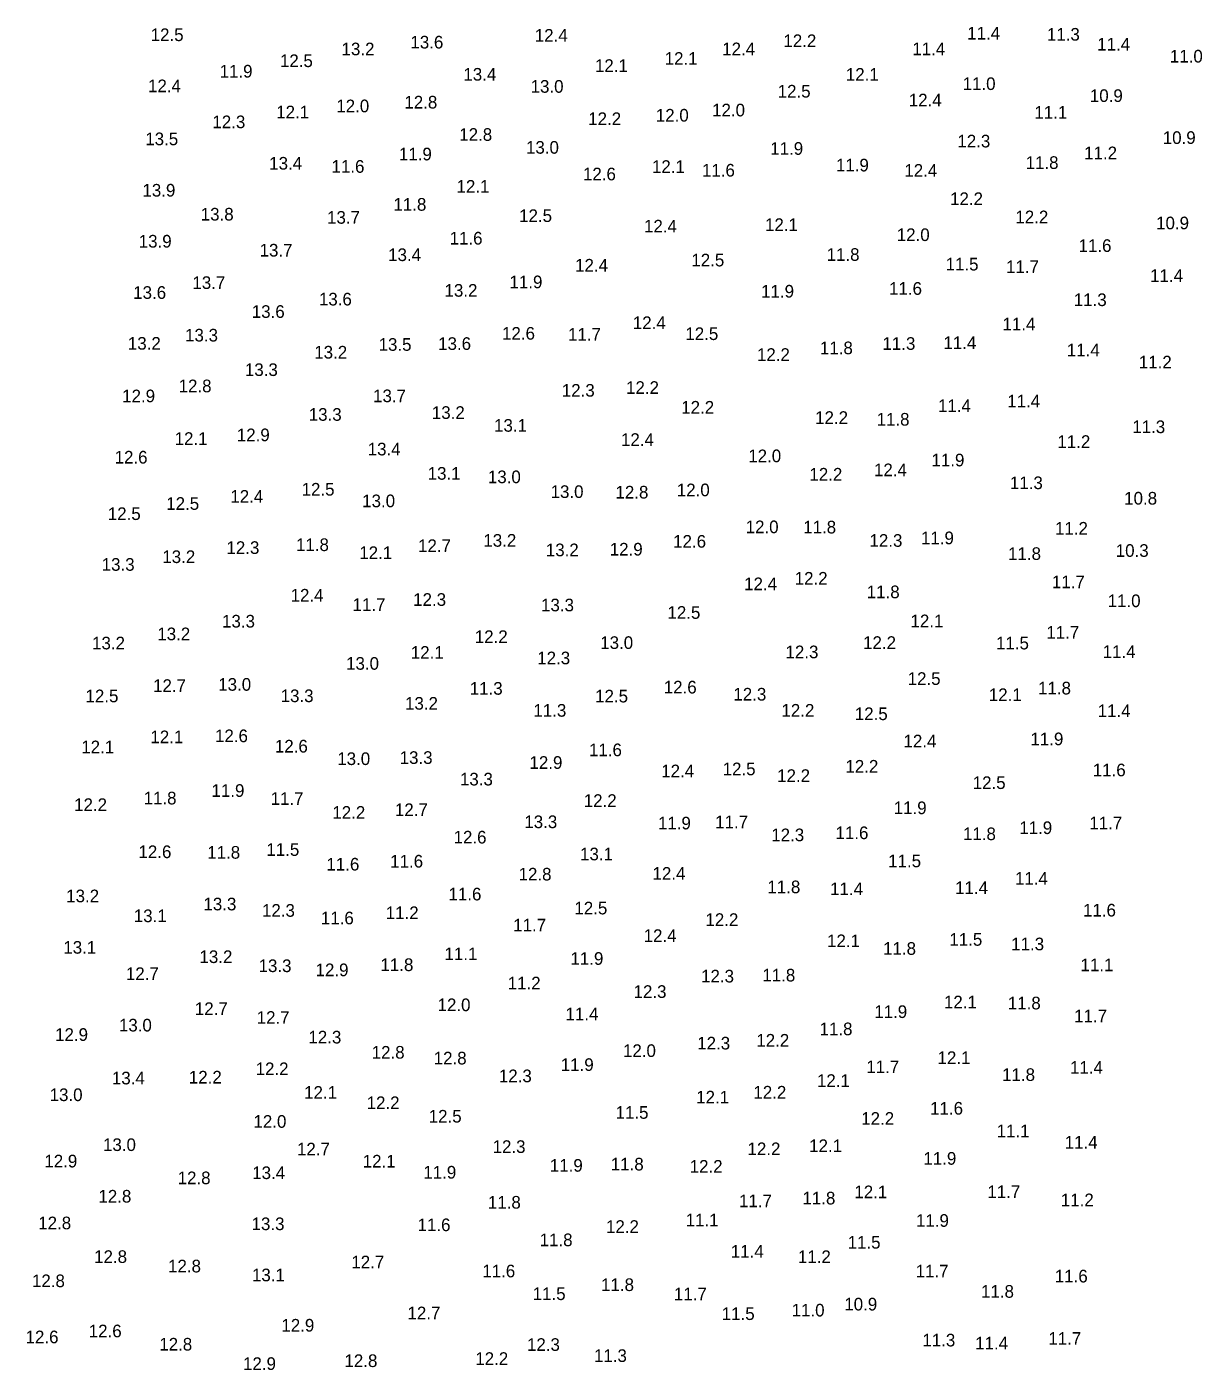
# Model space of a CAD drawing. Extents: x 1023796 to 1112670, y 656573 to 837340.
# Drawn here: x 1109778 to 1110243, y 670142 to 670673 of the extents above; entities that cross this region are included whole.
import ezdxf

# ---------------------------------------------------------------- set-up
doc = ezdxf.new("R2010")
doc.units = 0
doc.layers.add('V-TOPO-SOUN', color=7, linetype='Continuous')

msp = doc.modelspace()

# ---------------------------------------------------------------- texts
at = {"layer": 'V-TOPO-SOUN'}
for s, p in [('12.5 ', (1109827.08, 670667.24)), ('12.4 ', (1109978.96, 670667.01)), ('11.4 ', (1110149.93, 670667.86)), ('11.3 ', (1110181.44, 670667.41)), ('13.2 ', (1109902.55, 670661.62)), ('13.6 ', (1109929.78, 670664.31)), ('12.4 ', (1110053.06, 670661.65)), ('12.2 ', (1110077.26, 670664.86)), ('11.4 ', (1110128.21, 670661.67)), ('11.4 ', (1110201.33, 670663.51)), ('12.5 ', (1109878.19, 670656.96)), ('12.1 ', (1110030.31, 670657.86)), ('11.0 ', (1110230.06, 670658.76)), ('11.9 ', (1109854.34, 670652.82)), ('13.4 ', (1109950.73, 670651.6)), ('12.1 ', (1110002.74, 670655.04)), ('12.1 ', (1110101.95, 670651.57)), ('12.4 ', (1109826.04, 670647.03)), ('13.0 ', (1109977.31, 670646.81)), ('12.5 ', (1110074.99, 670644.91)), ('11.0 ', (1110148.12, 670647.89)), ('12.8 ', (1109927.4, 670640.58)), ('12.4 ', (1110126.83, 670641.41)), ('10.9 ', (1110198.43, 670643.16)), ('12.1 ', (1109876.73, 670636.7)), ('12.0 ', (1109900.48, 670639.1)), ('12.0 ', (1110026.81, 670635.41)), ('12.0 ', (1110049.06, 670637.47)), ('11.1 ', (1110176.49, 670636.57)), ('12.3 ', (1109851.49, 670632.8)), ('12.2 ', (1110000.08, 670634.04)), ('13.5 ', (1109824.95, 670626.07)), ('12.8 ', (1109949.09, 670627.8)), ('12.3 ', (1110146.04, 670625.18)), ('10.9 ', (1110227.25, 670626.57)), ('11.9 ', (1109925.23, 670620.07)), ('13.0 ', (1109975.48, 670622.71)), ('11.9 ', (1110072.05, 670622.27)), ('11.2 ', (1110196.17, 670620.52)), ('13.4 ', (1109873.95, 670616.43)), ('11.6 ', (1109898.59, 670615.18)), ('12.1 ', (1110025.28, 670615.12)), ('11.6 ', (1110045.05, 670613.67)), ('11.9 ', (1110098.02, 670615.71)), ('12.4 ', (1110125.07, 670613.6)), ('11.8 ', (1110173.02, 670616.7)), ('12.6 ', (1109998, 670612.18)), ('13.9 ', (1109823.83, 670605.76)), ('12.1 ', (1109948.02, 670607.29)), ('12.2 ', (1110143.16, 670602.4)), ('11.8 ', (1109923.07, 670600.17)), ('13.8 ', (1109846.88, 670596.29)), ('13.7 ', (1109896.83, 670595.02)), ('12.5 ', (1109972.77, 670595.71)), ('12.1 ', (1110069.99, 670592.15)), ('12.2 ', (1110168.98, 670595.21)), ('10.9 ', (1110224.62, 670592.82)), ('11.6 ', (1109945.28, 670586.8)), ('12.4 ', (1110022.14, 670591.56)), ('12.0 ', (1110122.08, 670588.18)), ('13.9 ', (1109822.37, 670585.6)), ('13.7 ', (1109870.15, 670582.05)), ('11.6 ', (1110193.95, 670583.87)), ('13.4 ', (1109920.98, 670580.26)), ('12.4 ', (1109994.9, 670576.11)), ('12.5 ', (1110040.86, 670578.15)), ('11.8 ', (1110094.34, 670580.35)), ('11.5 ', (1110141.38, 670576.54)), ('11.7 ', (1110165.28, 670575.5)), ('11.4 ', (1110222.25, 670572.03)), ('13.6 ', (1109820.18, 670565.32)), ('13.7 ', (1109843.59, 670569.23)), ('13.2 ', (1109943.27, 670566.17)), ('11.9 ', (1109968.96, 670569.51)), ('11.9 ', (1110068.45, 670565.82)), ('11.6 ', (1110119.03, 670566.92)), ('13.6 ', (1109893.61, 670562.71)), ('11.3 ', (1110192.07, 670562.46)), ('13.6 ', (1109867.06, 670557.8)), ('12.6 ', (1109966.01, 670549.18)), ('12.4 ', (1110017.72, 670553.37)), ('11.4 ', (1110163.88, 670552.85)), ('13.2 ', (1109818.07, 670545.23)), ('13.3 ', (1109840.68, 670548.46)), ('13.5 ', (1109917.2, 670544.78)), ('13.6 ', (1109940.75, 670545.13)), ('11.7 ', (1109992.1, 670548.77)), ('12.5 ', (1110038.49, 670549.04)), ('11.3 ', (1110116.42, 670545.16)), ('11.4 ', (1110140.53, 670545.46)), ('13.2 ', (1109891.76, 670541.72)), ('12.2 ', (1110066.8, 670540.79)), ('11.8 ', (1110091.69, 670543.43)), ('11.4 ', (1110189.31, 670542.59)), ('13.3 ', (1109864.34, 670534.82)), ('11.2 ', (1110217.78, 670537.8)), ('12.8 ', (1109838.14, 670528.39)), ('12.9 ', (1109815.82, 670524.43)), ('13.7 ', (1109915.02, 670524.47)), ('12.3 ', (1109989.64, 670526.65)), ('12.2 ', (1110015.04, 670527.75)), ('13.2 ', (1109938.26, 670517.86)), ('12.2 ', (1110036.86, 670519.94)), ('11.4 ', (1110138.37, 670520.56)), ('11.4 ', (1110165.75, 670522.39)), ('13.3 ', (1109889.59, 670517.11)), ('13.1 ', (1109962.85, 670512.79)), ('12.2 ', (1110089.8, 670515.88)), ('11.8 ', (1110114.1, 670515.2)), ('11.3 ', (1110215.19, 670512.24)), ('12.1 ', (1109836.55, 670507.57)), ('12.9 ', (1109861.15, 670509.03)), ('12.4 ', (1110013.04, 670507.18)), ('13.4 ', (1109912.9, 670503.43)), ('11.2 ', (1110185.59, 670506.39)), ('12.6 ', (1109812.83, 670500.21)), ('12.0 ', (1110063.36, 670500.73)), ('11.9 ', (1110135.81, 670499.09)), ('13.1 ', (1109936.61, 670493.81)), ('13.0 ', (1109960.42, 670492.44)), ('12.2 ', (1110087.54, 670493.47)), ('12.4 ', (1110113.07, 670495.2)), ('12.5 ', (1109886.76, 670487.53)), ('13.0 ', (1109985.21, 670486.59)), ('12.8 ', (1110010.86, 670486.38)), ('12.0 ', (1110035.11, 670487.27)), ('11.3 ', (1110166.81, 670490.08)), ('12.5 ', (1109833.24, 670481.9)), ('12.4 ', (1109858.58, 670484.72)), ('13.0 ', (1109910.71, 670482.94)), ('10.8 ', (1110212, 670483.98)), ('12.5 ', (1109810.14, 670477.88)), ('12.0 ', (1110062.33, 670472.66)), ('11.8 ', (1110085.09, 670472.57)), ('11.2 ', (1110184.64, 670472.1)), ('12.3 ', (1109857.05, 670464.47)), ('11.8 ', (1109884.54, 670465.61)), ('12.7 ', (1109932.81, 670465.22)), ('13.2 ', (1109958.63, 670467.32)), ('12.6 ', (1110033.66, 670466.94)), ('12.3 ', (1110111.29, 670467.28)), ('11.9 ', (1110131.65, 670468.3)), ('13.2 ', (1109831.69, 670460.86)), ('12.1 ', (1109909.56, 670462.45)), ('13.2 ', (1109983.32, 670463.56)), ('12.9 ', (1110008.6, 670463.83)), ('11.8 ', (1110166.09, 670462.09)), ('10.3 ', (1110208.66, 670463.31)), ('13.3 ', (1109807.72, 670457.8)), ('12.4 ', (1110061.73, 670450.13)), ('12.2 ', (1110081.72, 670452.33)), ('11.7 ', (1110183.41, 670450.92)), ('12.4 ', (1109882.41, 670445.63)), ('12.3 ', (1109930.87, 670443.94)), ('11.8 ', (1110110.21, 670446.96)), ('11.0 ', (1110205.46, 670443.43)), ('11.7 ', (1109906.9, 670441.92)), ('13.3 ', (1109981.43, 670441.77)), ('12.5 ', (1110031.41, 670438.81)), ('13.3 ', (1109855.3, 670435.37)), ('12.1 ', (1110127.51, 670435.48)), ('13.2 ', (1109829.71, 670430.35)), ('12.2 ', (1109955.24, 670429.25)), ('11.7 ', (1110181.21, 670430.96)), ('13.2 ', (1109803.92, 670426.73)), ('12.1 ', (1109929.94, 670423.01)), ('13.0 ', (1110004.83, 670426.9)), ('12.3 ', (1110078.08, 670423.23)), ('12.2 ', (1110108.77, 670426.91)), ('11.5 ', (1110161.31, 670426.72)), ('11.4 ', (1110203.48, 670423.33)), ('13.0 ', (1109904.35, 670418.68)), ('12.3 ', (1109979.93, 670420.83)), ('12.5 ', (1110126.38, 670412.68)), ('12.5 ', (1109801.32, 670405.82)), ('12.7 ', (1109828.04, 670409.9)), ('13.0 ', (1109853.8, 670410.37)), ('13.3 ', (1109878.47, 670405.87)), ('11.3 ', (1109953.25, 670408.8)), ('12.5 ', (1110002.82, 670405.74)), ('12.6 ', (1110029.95, 670409.29)), ('12.3 ', (1110057.48, 670406.5)), ('12.1 ', (1110158.48, 670406.29)), ('11.8 ', (1110177.94, 670408.91)), ('13.2 ', (1109927.66, 670402.89)), ('11.3 ', (1109978.41, 670400.11)), ('12.2 ', (1110076.48, 670400.13)), ('12.5 ', (1110105.49, 670398.76)), ('11.4 ', (1110201.52, 670399.95)), ('12.6 ', (1109852.52, 670390.04)), ('12.1 ', (1109799.64, 670385.65)), ('12.1 ', (1109826.98, 670389.63)), ('12.6 ', (1109876.2, 670385.95)), ('11.6 ', (1110000.39, 670384.49)), ('12.4 ', (1110124.75, 670387.98)), ('11.9 ', (1110174.93, 670388.82)), ('13.0 ', (1109900.86, 670381)), ('13.3 ', (1109925.53, 670381.45)), ('12.9 ', (1109976.86, 670379.49)), ('12.4 ', (1110028.95, 670376.16)), ('12.5 ', (1110053.23, 670376.96)), ('12.2 ', (1110074.79, 670374.31)), ('12.2 ', (1110101.78, 670377.99)), ('11.6 ', (1110199.57, 670376.54)), ('13.3 ', (1109949.37, 670372.92)), ('12.5 ', (1110152.09, 670371.52)), ('11.8 ', (1109824.29, 670365.43)), ('11.9 ', (1109851.14, 670368.42)), ('11.7 ', (1109874.5, 670365.25)), ('12.2 ', (1109998.32, 670364.44)), ('12.2 ', (1109796.82, 670362.83)), ('12.2 ', (1109898.91, 670359.75)), ('12.7 ', (1109923.65, 670360.81)), ('11.9 ', (1110120.87, 670361.58)), ('13.3 ', (1109974.82, 670356.05)), ('11.9 ', (1110027.65, 670355.55)), ('11.7 ', (1110050.28, 670356)), ('11.9 ', (1110170.51, 670353.71)), ('11.7 ', (1110198.2, 670355.57)), ('12.6 ', (1109946.85, 670349.98)), ('12.3 ', (1110072.45, 670350.88)), ('11.6 ', (1110097.86, 670351.7)), ('11.8 ', (1110148.25, 670351.3)), ('12.6 ', (1109822.26, 670344.2)), ('11.8 ', (1109849.45, 670343.97)), ('11.5 ', (1109872.83, 670345.09)), ('13.1 ', (1109996.86, 670343.32)), ('11.6 ', (1109896.57, 670339.29)), ('11.6 ', (1109921.79, 670340.46)), ('11.5 ', (1110118.68, 670340.59)), ('12.8 ', (1109972.55, 670335.35)), ('12.4 ', (1110025.51, 670335.64)), ('11.4 ', (1110168.8, 670333.68)), ('13.2 ', (1109793.68, 670326.74)), ('11.6 ', (1109944.84, 670327.48)), ('11.8 ', (1110070.93, 670330.32)), ('11.4 ', (1110095.73, 670329.55)), ('11.4 ', (1110145.15, 670330)), ('13.3 ', (1109847.95, 670323.54)), ('12.3 ', (1109871.1, 670321.01)), ('12.5 ', (1109994.62, 670321.94)), ('11.6 ', (1110195.72, 670321.11)), ('13.1 ', (1109820.41, 670318.88)), ('11.6 ', (1109894.38, 670318.02)), ('11.2 ', (1109920.03, 670320.08)), ('12.2 ', (1110046.43, 670317.38)), ('11.7 ', (1109970.42, 670315.2)), ('12.4 ', (1110021.99, 670311.04)), ('13.1 ', (1109792.56, 670306.41)), ('12.1 ', (1110094.52, 670308.99)), ('11.8 ', (1110116.67, 670305.97)), ('11.5 ', (1110142.87, 670309.54)), ('11.3 ', (1110167.32, 670307.75)), ('13.2 ', (1109846.38, 670302.71)), ('11.8 ', (1109917.94, 670299.54)), ('11.1 ', (1109943.26, 670303.85)), ('11.9 ', (1109993.06, 670302)), ('12.7 ', (1109817.29, 670296)), ('13.3 ', (1109869.75, 670299.13)), ('12.9 ', (1109892.28, 670297.51)), ('12.3 ', (1110044.71, 670295.03)), ('11.8 ', (1110068.93, 670295.42)), ('11.1 ', (1110194.73, 670299.48)), ('11.2 ', (1109968.26, 670292.28)), ('12.3 ', (1110018.01, 670288.93)), ('12.0 ', (1109940.52, 670283.69)), ('12.1 ', (1110140.72, 670284.78)), ('11.8 ', (1110165.99, 670284.39)), ('12.7 ', (1109844.56, 670282.17)), ('12.7 ', (1109869, 670278.68)), ('11.4 ', (1109991.1, 670280.07)), ('11.9 ', (1110113.18, 670280.98)), ('11.7 ', (1110192.21, 670279.27)), ('13.0 ', (1109814.53, 670275.65)), ('11.8 ', (1110091.55, 670274.17)), ('12.9 ', (1109789.3, 670271.93)), ('12.3 ', (1109889.45, 670270.91)), ('12.3 ', (1110043.18, 670268.53)), ('12.2 ', (1110066.54, 670269.66)), ('12.8 ', (1109914.47, 670264.91)), ('12.8 ', (1109938.99, 670262.61)), ('12.0 ', (1110013.83, 670265.57)), ('12.1 ', (1110138.2, 670262.79)), ('12.2 ', (1109868.57, 670258.39)), ('11.9 ', (1109989.24, 670260.04)), ('11.7 ', (1110110.03, 670259.17)), ('11.4 ', (1110190.57, 670258.93)), ('13.4 ', (1109811.75, 670254.74)), ('12.2 ', (1109842.18, 670255.08)), ('12.3 ', (1109964.76, 670255.59)), ('12.1 ', (1110090.52, 670253.73)), ('11.8 ', (1110163.73, 670256.09)), ('13.0 ', (1109787.14, 670248.13)), ('12.1 ', (1109887.75, 670249.04)), ('12.1 ', (1110042.78, 670247.18)), ('12.2 ', (1110065.39, 670249.13)), ('12.2 ', (1109912.47, 670244.95)), ('11.5 ', (1110010.9, 670241.13)), ('11.6 ', (1110135.27, 670242.78)), ('12.0 ', (1109867.73, 670237.57)), ('12.5 ', (1109937.02, 670239.63)), ('12.2 ', (1110108.02, 670238.75)), ('11.1 ', (1110161.57, 670233.84)), ('13.0 ', (1109808.24, 670228.39)), ('12.7 ', (1109884.92, 670226.64)), ('12.3 ', (1109962.28, 670227.62)), ('12.2 ', (1110063.06, 670226.75)), ('12.1 ', (1110087.44, 670227.96)), ('11.4 ', (1110188.49, 670229.35)), ('12.9 ', (1109785.05, 670221.9)), ('12.1 ', (1109910.92, 670221.86)), ('11.9 ', (1109984.91, 670220.21)), ('11.8 ', (1110009.01, 670220.7)), ('12.2 ', (1110040.2, 670219.82)), ('11.9 ', (1110132.61, 670222.96)), ('12.8 ', (1109837.75, 670215.27)), ('13.4 ', (1109867.24, 670217.29)), ('11.9 ', (1109934.89, 670217.49)), ('12.1 ', (1110105.31, 670209.73)), ('11.7 ', (1110157.92, 670209.8)), ('12.8 ', (1109806.43, 670208)), ('11.8 ', (1109960.41, 670205.61)), ('11.7 ', (1110059.72, 670206.17)), ('11.8 ', (1110084.78, 670207.26)), ('11.2 ', (1110186.95, 670206.55)), ('12.8 ', (1109782.63, 670197.44)), ('13.3 ', (1109866.98, 670197.1)), ('11.6 ', (1109932.61, 670196.7)), ('12.2 ', (1110007.11, 670196.02)), ('11.1 ', (1110038.59, 670198.61)), ('11.9 ', (1110129.67, 670198.41)), ('11.8 ', (1109980.88, 670190.76)), ('11.5 ', (1110102.65, 670189.79)), ('12.8 ', (1109804.73, 670184.13)), ('11.4 ', (1110056.46, 670186.22)), ('11.2 ', (1110082.99, 670184.08)), ('12.8 ', (1109833.96, 670180.39)), ('12.7 ', (1109906.42, 670182)), ('11.6 ', (1109958.2, 670178.44)), ('11.7 ', (1110129.53, 670178.39)), ('12.8 ', (1109780.15, 670174.56)), ('13.1 ', (1109867.13, 670176.88)), ('11.8 ', (1110005.17, 670173.03)), ('11.6 ', (1110184.56, 670176.42)), ('11.5 ', (1109978.12, 670169.46)), ('11.7 ', (1110033.95, 670169.34)), ('11.8 ', (1110155.39, 670170.38)), ('12.7 ', (1109928.63, 670161.86)), ('11.5 ', (1110052.88, 670161.57)), ('11.0 ', (1110080.51, 670162.96)), ('10.9 ', (1110101.33, 670165.34)), ('12.9 ', (1109878.77, 670156.99)), ('12.6 ', (1109777.62, 670152.37)), ('12.6 ', (1109802.6, 670154.73)), ('11.3 ', (1110132.2, 670151.12)), ('11.7 ', (1110182, 670151.77)), ('12.8 ', (1109830.49, 670149.5)), ('12.3 ', (1109975.87, 670149.37)), ('11.4 ', (1110153.07, 670149.92)), ('12.9 ', (1109863.6, 670141.82)), ('12.8 ', (1109903.71, 670142.98)), ('12.2 ', (1109955.43, 670143.82)), ('11.3 ', (1110002.35, 670144.98))]:
    msp.add_text(s, height=5, dxfattribs=at).set_placement(p)

doc.saveas('drawing.dxf')
